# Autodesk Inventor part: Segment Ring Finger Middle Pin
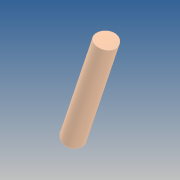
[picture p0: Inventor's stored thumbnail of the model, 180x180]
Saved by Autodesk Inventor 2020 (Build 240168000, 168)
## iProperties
Created: 2019-10
Part Number: Segment Ring Finger Middle Pin
Material: GFRP
Document SubType Name: Modeling
Designer: yello
Density: 1.75 g/cm^3
Appearance: Default
Author: yello
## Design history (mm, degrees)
feature "Paliczek SE"
sketch "Sketch1"
  geometry: C1 r 2 at (0, 0); C2 r 50 at (0, 0); 1 further point
  constraints: 2 centre point, 1 coincident
  dimensions: "d0" = 4 diameter of C1; "d1" = 100 diameter of C2
extrude "Extrusion1" cut sketch "Sketch1" stored distance "d2" = 100; taper "d3" = 0 deg
loft "Loft1" dims "d4" = 0, "d5" = 90 deg, "d6" = 0, "d7" = 90 deg
  node "Edges1"
  node "Edges2"
body "Solid1"
